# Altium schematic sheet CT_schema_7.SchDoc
size 296 x 173 mm
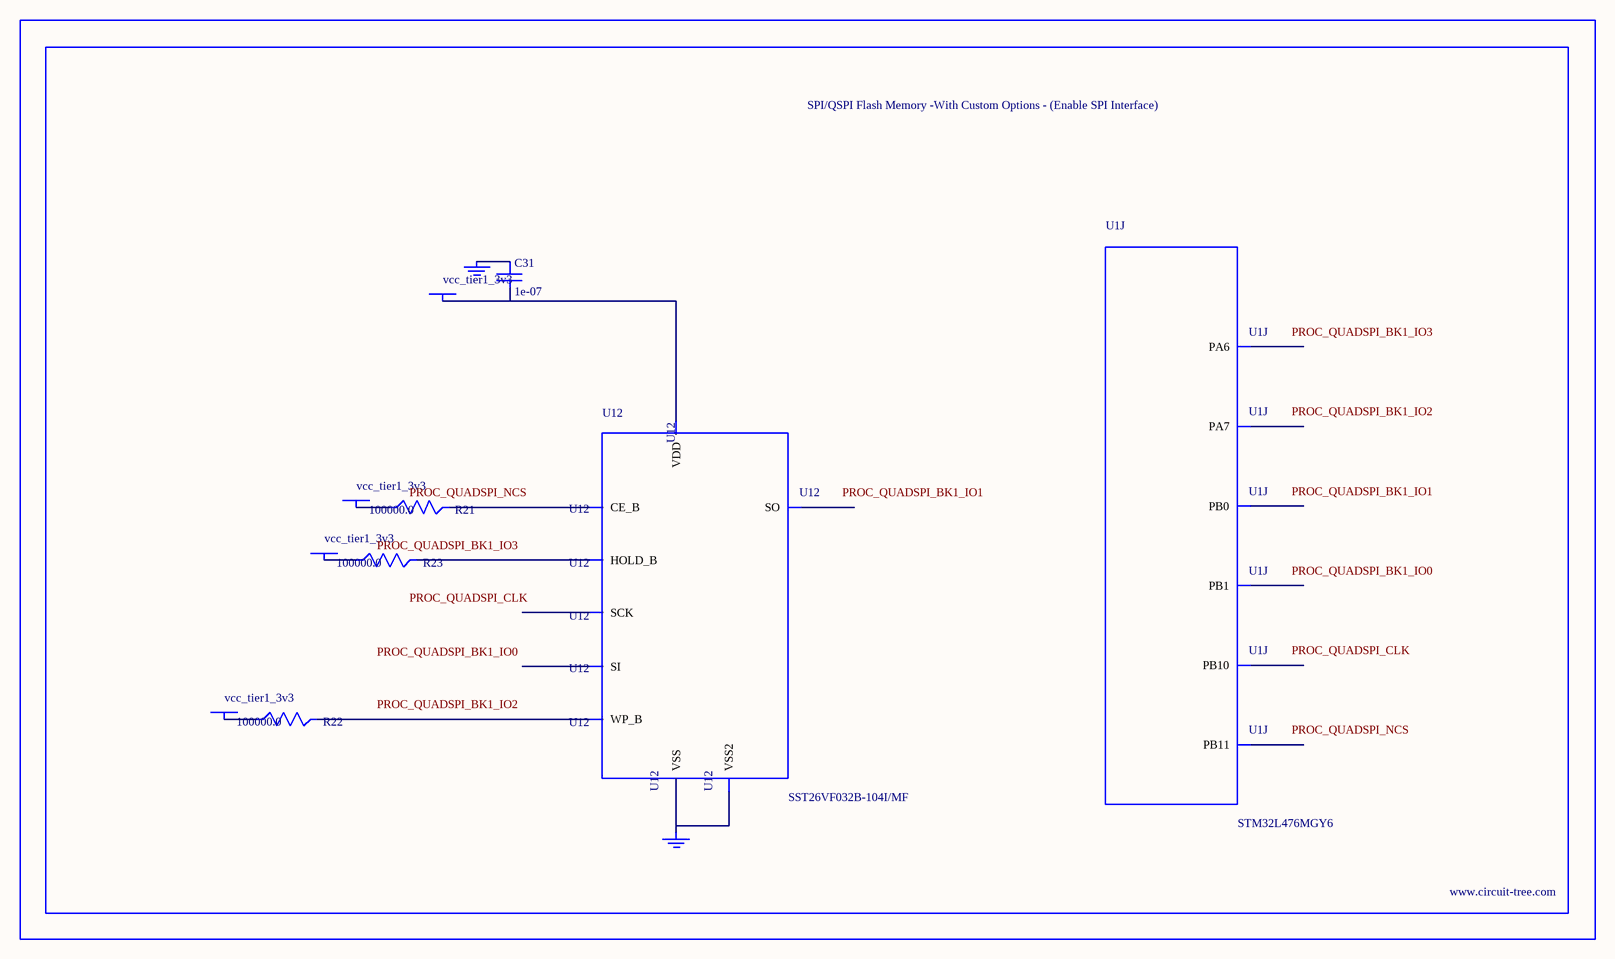
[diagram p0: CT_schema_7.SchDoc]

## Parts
BORDER6  (no value)
C31  1e-07  [C0402]
GND_INSTANCE_6_0  (no value)
GND_INSTANCE_6_1  (no value)
POWER_INSTANCE_6_0  vcc_tier1_3v3
POWER_INSTANCE_6_1  vcc_tier1_3v3
POWER_INSTANCE_6_2  vcc_tier1_3v3
POWER_INSTANCE_6_3  vcc_tier1_3v3
R21  100000.0  [R0603]
R22  100000.0  [R0603]
R23  100000.0  [R0603]
U1  STM32L476MGY6  [WLCSP81]  (part J of 10)
U12  SST26VF032B-104I/MF  [WFDN-8]

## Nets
NetC31_1: C31.1 GND_INSTANCE_6_0.0(GND)
NetC31_2: C31.2 POWER_INSTANCE_6_3.0(PWR) U12.8(VDD)
NetGND_INSTANCE_6_1_0: GND_INSTANCE_6_1.0(GND) U12.4(VSS) U12.9(VSS2)
NetPOWER_INSTANCE_6_0_0: POWER_INSTANCE_6_0.0(PWR) R21.1
NetPOWER_INSTANCE_6_1_0: POWER_INSTANCE_6_1.0(PWR) R22.1
NetPOWER_INSTANCE_6_2_0: POWER_INSTANCE_6_2.0(PWR) R23.1
NetR21_2: R21.2 U12.1(CE_B)
NetR22_2: R22.2 U12.3(WP_B)
NetR23_2: R23.2 U12.7(HOLD_B)

Not connected (* = marked no-connect by the designer): U1 G3(PB11) H3(PB10) H4(PA7) H5(PA6) J4(PB1) J5(PB0); U12 2(SO) 5(SI) 6(SCK)

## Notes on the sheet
- Labels drawn without touching a wire or pin: PROC_QUADSPI_BK1_IO0, PROC_QUADSPI_BK1_IO1, PROC_QUADSPI_BK1_IO2, PROC_QUADSPI_BK1_IO3, PROC_QUADSPI_CLK, PROC_QUADSPI_NCS

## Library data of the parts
BORDER6 = BORDER_PAGE6
C31 = C0402C104K3RACTU
GND_INSTANCE_6_0 GND_INSTANCE_6_1 = GND
POWER_INSTANCE_6_0-POWER_INSTANCE_6_3 = PWR
R21-R23 = RC0603JR-07100KL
